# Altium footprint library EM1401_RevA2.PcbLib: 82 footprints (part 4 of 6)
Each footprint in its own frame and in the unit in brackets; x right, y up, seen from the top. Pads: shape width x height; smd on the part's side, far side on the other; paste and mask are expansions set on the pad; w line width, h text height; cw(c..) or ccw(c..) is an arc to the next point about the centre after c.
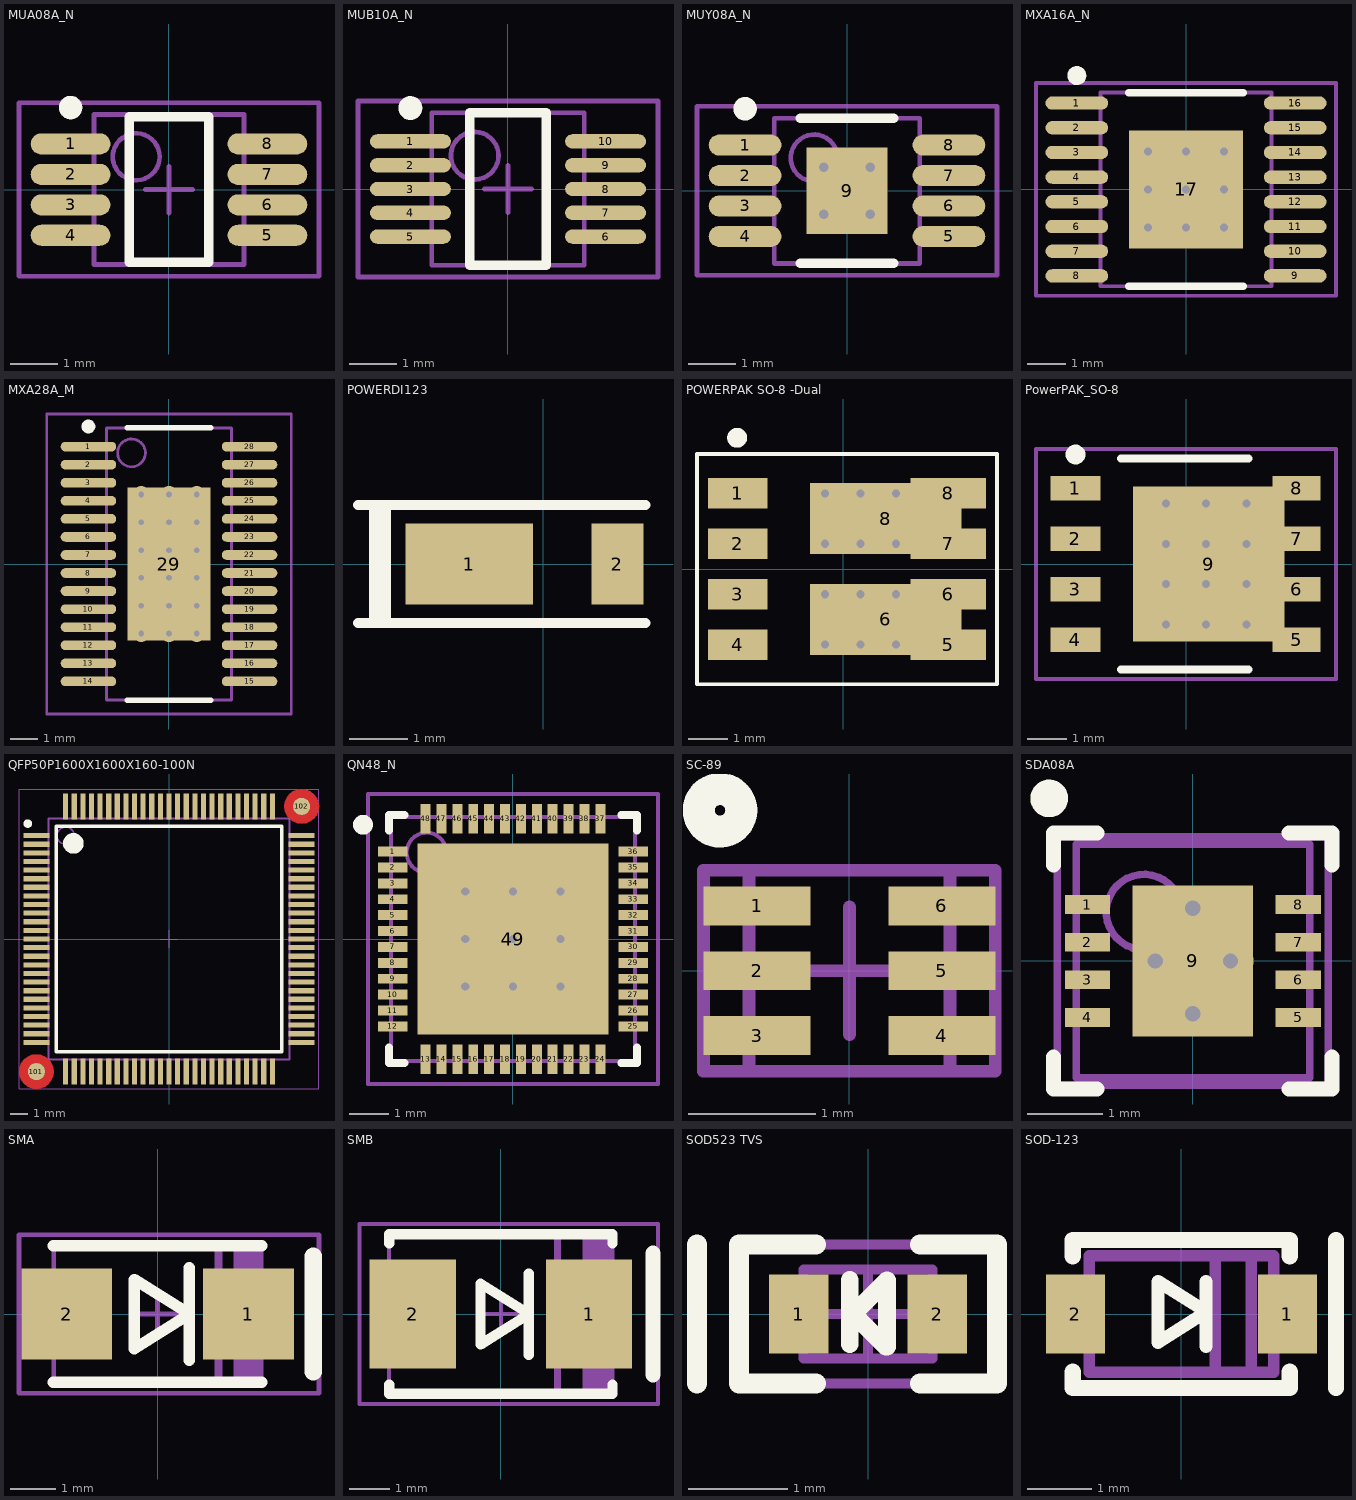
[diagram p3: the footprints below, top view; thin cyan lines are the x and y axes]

## MUA08A_N [mm] "TSOP, 8-Leads, Body 3x3mm, Pitch 0.65mm, IPC Medium Density"
height 1.09
pads (8):
  oval 1.7x0.45 smd: 1(-2.1,0.975) 2(-2.1,0.325) 3(-2.1,-0.325) 4(-2.1,-0.975) 5(2.1,-0.975) 6(2.1,-0.325) 7(2.1,0.325) 8(2.1,0.975)
Top Overlay:
  circle w0.25: c-2.1,1.75 r0.125
  lines w0.2: -0.85,-1.55 0.85,-1.55 0.85,1.55 -0.85,1.55 -0.85,-1.55
Mechanical 5:
  text ".Designator" at -1.524,-0.508 h1.02
Mechanical 13:
  circle w0.1: c-0.7,0.7 r0.5
  lines w0.1: -1.6,-1.6 1.6,-1.6 1.6,1.6 -1.6,1.6 -1.6,-1.6
Mechanical 15:
  lines w0.1: -0.5,0 0.5,0 ; 0,-0.5 0,0.5 ; -3.2,-1.85 3.2,-1.85 3.2,1.85 -3.2,1.85 -3.2,-1.85
3D body: height 1.09, standoff 0, extent -1.6,-1.6 1.6,1.6

## MUB10A_N [mm] "TSSOP, 10-Leads, Body 3x3mm, Pitch 0.5mm, IPC Medium Density"
height 1.09
pads (10):
  oval 1.7x0.3 smd: 1(-2.05,1) 2(-2.05,0.5) 3(-2.05,0) 4(-2.05,-0.5) 5(-2.05,-1) 6(2.05,-1) 7(2.05,-0.5) 8(2.05,0) 9(2.05,0.5) 10(2.05,1)
Top Overlay:
  circle w0.25: c-2.05,1.7 r0.125
  lines w0.2: -0.8,-1.6 -0.8,1.6 0.8,1.6 0.8,-1.6 -0.8,-1.6
Mechanical 5:
  text ".Designator" at -1.524,-0.508 h1.02
Mechanical 13:
  circle w0.1: c-0.7,0.7 r0.5
  lines w0.1: -1.6,-1.6 -1.6,1.6 1.6,1.6 1.6,-1.6 -1.6,-1.6
Mechanical 15:
  lines w0.1: -0.5,0 0.5,0 ; 0,-0.5 0,0.5 ; -3.15,-1.85 -3.15,1.85 3.15,1.85 3.15,-1.85 -3.15,-1.85
3D body: height 1.09, standoff 0, extent -1.6,-1.6 1.6,1.6

## MUY08A_N [mm] "TSOP, 8-Leads, Body 3x3mm, Pitch 0.65mm, Exposed Pad, IPC Medium Density"
height 1.09
pads (9):
  oval 1.55x0.45 smd: 1(-2.175,0.975) 2(-2.175,0.325) 3(-2.175,-0.325) 4(-2.175,-0.975) 5(2.175,-0.975) 6(2.175,-0.325) 7(2.175,0.325) 8(2.175,0.975)
  rect 1.73x1.85 smd: 9(0,0)
via 0.5,-0.5 diameter 0.61 hole 0.203
via -0.5,-0.5 diameter 0.61 hole 0.203
via -0.5,0.5 diameter 0.61 hole 0.203
via 0.5,0.5 diameter 0.61 hole 0.203
Top Overlay:
  circle w0.25: c-2.175,1.75 r0.125
  lines w0.2: -1,-1.55 1,-1.55 ; -1,1.55 1,1.55
Mechanical 5:
  text ".Designator" at -1.524,-0.508 h1.02
Mechanical 13:
  circle w0.1: c-0.7,0.7 r0.5
  lines w0.1: -1.55,-1.55 1.55,-1.55 1.55,1.55 -1.55,1.55 -1.55,-1.55
Mechanical 15:
  lines w0.1: -0.5,0 0.5,0 ; 0,-0.5 0,0.5 ; -3.2,-1.8 3.2,-1.8 3.2,1.8 -3.2,1.8 -3.2,-1.8
3D body: height 1.09, standoff 0, extent -1.549,-1.549 1.549,1.549

## MXA16A_N [mm] "TSOP, 16-Leads, Body 5x4.4mm, Pitch 0.65mm, Exposed Pad, IPC Medium Density"
height 1.1
pads (17):
  oval 1.65x0.35 smd: 1(-2.875,2.275) 2(-2.875,1.625) 3(-2.875,0.975) 4(-2.875,0.325) 5(-2.875,-0.325) 6(-2.875,-0.975) 7(-2.875,-1.625) 8(-2.875,-2.275) 9(2.875,-2.275) 10(2.875,-1.625) 11(2.875,-0.975) 12(2.875,-0.325) 13(2.875,0.325) 14(2.875,0.975) 15(2.875,1.625) 16(2.875,2.275)
  rect 3x3.1 smd: 17(0,0)
via -1,-1 diameter 0.61 hole 0.203
via 0,-1 diameter 0.61 hole 0.203
via -1,0 diameter 0.61 hole 0.203
via 0,0 diameter 0.61 hole 0.203
via 1,-1 diameter 0.61 hole 0.203
via 1,0 diameter 0.61 hole 0.203
via 0,1 diameter 0.61 hole 0.203
via -1,1 diameter 0.61 hole 0.203
via 1,1 diameter 0.61 hole 0.203
Top Overlay:
  circle w0.25: c-2.875,3 r0.125
  lines w0.2: -1.5,-2.55 1.5,-2.55 ; -1.5,2.55 1.5,2.55
Mechanical 5:
  text ".Designator" at -1.524,-0.508 h1.02
Mechanical 13:
  lines w0.1: -2.25,-2.55 2.25,-2.55 2.25,2.55 -2.25,2.55 -2.25,-2.55
Mechanical 15:
  lines w0.1: -0.5,0 0.5,0 ; 0,-0.5 0,0.5 ; -3.95,-2.8 3.95,-2.8 3.95,2.8 -3.95,2.8 -3.95,-2.8
3D body: height 1.1, standoff 0, extent -2.25,-2.55 2.25,2.55

## MXA28A_M [mm] "TSOP, 28-Leads, Body 9.7x4.4mm, Pitch 0.65mm, Exposed Pad, IPC Low Density"
height 1.1
pads (29):
  oval 2x0.35 smd: 1(-2.9,4.225) 2(-2.9,3.575) 3(-2.9,2.925) 4(-2.9,2.275) 5(-2.9,1.625) 6(-2.9,0.975) 7(-2.9,0.325) 8(-2.9,-0.325) 9(-2.9,-0.975) 10(-2.9,-1.625) 11(-2.9,-2.275) 12(-2.9,-2.925) 13(-2.9,-3.575) 14(-2.9,-4.225) 15(2.9,-4.225) 16(2.9,-3.575) 17(2.9,-2.925) 18(2.9,-2.275) 19(2.9,-1.625) 20(2.9,-0.975) 21(2.9,-0.325) 22(2.9,0.325) 23(2.9,0.975) 24(2.9,1.625) 25(2.9,2.275) 26(2.9,2.925) 27(2.9,3.575) 28(2.9,4.225)
  rect 3x5.5 smd: 29(0,0)
via 1,2.5 diameter 0.61 hole 0.203
via 1,1.5 diameter 0.61 hole 0.203
via 1,0.5 diameter 0.61 hole 0.203
via 1,-0.5 diameter 0.61 hole 0.203
via 1,-1.5 diameter 0.61 hole 0.203
via 1,-2.5 diameter 0.61 hole 0.203
via 0,2.5 diameter 0.61 hole 0.203
via 0,1.5 diameter 0.61 hole 0.203
via -1,2.5 diameter 0.61 hole 0.203
via -1,1.5 diameter 0.61 hole 0.203
via 0,0.5 diameter 0.61 hole 0.203
via -1,0.5 diameter 0.61 hole 0.203
via 0,-0.5 diameter 0.61 hole 0.203
via 0,-1.5 diameter 0.61 hole 0.203
via 0,-2.5 diameter 0.61 hole 0.203
via -1,-0.5 diameter 0.61 hole 0.203
via -1,-1.5 diameter 0.61 hole 0.203
via -1,-2.5 diameter 0.61 hole 0.203
Top Overlay:
  circle w0.25: c-2.9,4.95 r0.125
  lines w0.2: -1.5,-4.9 1.5,-4.9 ; -1.5,4.9 1.5,4.9
Mechanical 5:
  text ".Designator" at -1.524,-0.508 h1.02
Mechanical 13:
  circle w0.1: c-1.35,4 r0.5
  lines w0.1: -2.25,-4.9 2.25,-4.9 2.25,4.9 -2.25,4.9 -2.25,-4.9
Mechanical 15:
  lines w0.1: -4.4,-5.4 4.4,-5.4 4.4,5.4 -4.4,5.4 -4.4,-5.4 ; -0.5,0 0.5,0 -0.5,0 ; 0,-0.5 0,0.5 0,-0.5
3D body: height 1.1, standoff 0.05, extent -2.25,-4.9 2.25,4.9

## POWERDI123 [mm] "Diodes Inc recommended land pattern, document number DS30628 Rev. 6-2"
height 1
pads (2):
  rect 2.2x1.4 smd: 1(-1.275,0)
  rect 0.9x1.4 smd: 2(1.275,0)
Top Overlay:
  lines w0.178: -3.194,-1.016 1.759,-1.016 ; -3.194,1.016 1.759,1.016
  lines w0.381: -2.813,-0.889 -2.813,0.889
Mechanical 5:
  text ".Designator" at -1.524,-0.508 h1.02
3D body: height 1, standoff 0.9, extent -1.299,-0.799 -1.101,0.699
3D body: height 1, standoff 0, extent -1.499,-0.969 1.499,0.959

## POWERPAK SO-8 -Dual [mm] "Dual N-CHANNEL 40V MOSFET, POWERPAK SO-8 , VISHAY"
height 3.5
pads (10):
  rect 1.5x0.762 smd mask+0.076: 1(-2.65,1.905) 2(-2.65,0.635) 3(-2.65,-0.635) 4(-2.65,-1.905)
  rect 1.9x0.762 smd mask+0.076: 5(2.65,-1.905) 6(2.65,-0.635) 7(2.65,0.635) 8(2.65,1.905)
  rect 3.81x1.778 smd: 6(1.075,-1.27) 8(1.075,1.27)
via 0.44,-1.905 diameter 0.406 hole 0.203
via 1.329,-1.905 diameter 0.406 hole 0.203
via 1.329,-0.635 diameter 0.406 hole 0.203
via 1.329,0.635 diameter 0.406 hole 0.203
via 0.44,-0.635 diameter 0.406 hole 0.203
via -0.449,-1.905 diameter 0.406 hole 0.203
via -0.449,-0.635 diameter 0.406 hole 0.203
via -0.449,0.635 diameter 0.406 hole 0.203
via 0.44,0.635 diameter 0.406 hole 0.203
via 0.44,1.905 diameter 0.406 hole 0.203
via 1.329,1.905 diameter 0.406 hole 0.203
via -0.449,1.905 diameter 0.406 hole 0.203
Top Overlay:
  circle w0.25: c-2.665,3.302 r0.125
  lines w0.1: -3.675,-2.9 3.875,-2.9 3.875,2.9 -3.675,2.9 -3.675,-2.9
Mechanical 5:
  text ".designator" at 0.465,-2.08 h1.02

## PowerPAK_SO-8 [mil] "Vishay PowerPAK SO-8, Body 5.3x6.0mm (max), Pitch 1.27mm, IPC Medium Density"
height 44.09
pads (9):
  rect 50x24 smd mask+2.99: 1(-109.5,75) 2(-109.5,25) 3(-109.5,-25) 4(-109.5,-75)
  rect 48x24 smd mask+2.99: 5(109.5,-75) 8(109.5,75)
  rect 48x24 smd paste-12 mask+2.99: 6(109.5,-25) 7(109.5,25)
  rect 150x154 smd paste-75 mask+2.99: 9(22.5,0)
via 20,60 diameter 28 hole 8
via -20,60 diameter 28 hole 8
via -20,20 diameter 28 hole 8
via 20,20 diameter 28 hole 8
via 60,60 diameter 28 hole 8
via 60,20 diameter 28 hole 8
via -20,-20 diameter 28 hole 8
via 60,-20 diameter 28 hole 8
via 20,-20 diameter 28 hole 8
via 20,-60 diameter 28 hole 8
via -20,-60 diameter 28 hole 8
via 60,-60 diameter 28 hole 8
Top Overlay:
  circle w9.84: c-109.5,108.46 r4.92
  lines w7.87: -64.22,-104.33 61.76,-104.33 ; -64.22,104.33 61.76,104.33
Top Paste:
  rectangle: -47,2.5 20.5,72
  rectangle: 25.5,2.5 93,72
  rectangle: 97.5,13 133,37
  rectangle: 97.5,-37 133,-13
  rectangle: -47.5,-72 20,-2.5
  rectangle: 25,-72 92.5,-2.5
Mechanical 5:
  text ".Designator" at -60,-20 h40
Mechanical 15:
  lines w3.94: -19.68,0 19.68,0 ; 0,-19.68 0,19.68 ; -148.62,-114.17 -148.62,114.17 148.62,114.17 148.62,-114.17 -148.62,-114.17
3D body: height 42.6, standoff 0.6, extent -120.84,-101.5 121.16,101.5

## QFP50P1600X1600X160-100N [mm]
pads (102):
  rect 1.5x0.3 smd: 1(-7.7,6) 2(-7.7,5.5) 3(-7.7,5) 4(-7.7,4.5) 5(-7.7,4) 6(-7.7,3.5) 7(-7.7,3) 8(-7.7,2.5) 9(-7.7,2) 10(-7.7,1.5) 11(-7.7,1) 12(-7.7,0.5) 13(-7.7,0) 14(-7.7,-0.5) 15(-7.7,-1) 16(-7.7,-1.5) 17(-7.7,-2) 18(-7.7,-2.5) 19(-7.7,-3) 20(-7.7,-3.5) 21(-7.7,-4) 22(-7.7,-4.5) 23(-7.7,-5) 24(-7.7,-5.5) 25(-7.7,-6) 51(7.7,-6) 52(7.7,-5.5) 53(7.7,-5) 54(7.7,-4.5) 55(7.7,-4) 56(7.7,-3.5) 57(7.7,-3) 58(7.7,-2.5) 59(7.7,-2) 60(7.7,-1.5) 61(7.7,-1) 62(7.7,-0.5) 63(7.7,0) 64(7.7,0.5) 65(7.7,1) 66(7.7,1.5) 67(7.7,2) 68(7.7,2.5) 69(7.7,3) 70(7.7,3.5) 71(7.7,4) 72(7.7,4.5) 73(7.7,5) 74(7.7,5.5) 75(7.7,6)
  rect 0.3x1.5 smd: 26(-6,-7.7) 27(-5.5,-7.7) 28(-5,-7.7) 29(-4.5,-7.7) 30(-4,-7.7) 31(-3.5,-7.7) 32(-3,-7.7) 33(-2.5,-7.7) 34(-2,-7.7) 35(-1.5,-7.7) 36(-1,-7.7) 37(-0.5,-7.7) 38(0,-7.7) 39(0.5,-7.7) 40(1,-7.7) 41(1.5,-7.7) 42(2,-7.7) 43(2.5,-7.7) 44(3,-7.7) 45(3.5,-7.7) 46(4,-7.7) 47(4.5,-7.7) 48(5,-7.7) 49(5.5,-7.7) 50(6,-7.7) 76(6,7.7) 77(5.5,7.7) 78(5,7.7) 79(4.5,7.7) 80(4,7.7) 81(3.5,7.7) 82(3,7.7) 83(2.5,7.7) 84(2,7.7) 85(1.5,7.7) 86(1,7.7) 87(0.5,7.7) 88(0,7.7) 89(-0.5,7.7) 90(-1,7.7) 91(-1.5,7.7) 92(-2,7.7) 93(-2.5,7.7) 94(-3,7.7) 95(-3.5,7.7) 96(-4,7.7) 97(-4.5,7.7) 98(-5,7.7) 99(-5.5,7.7) 100(-6,7.7)
  round 1 smd mask+0.5: 101(-7.7,-7.7) 102(7.7,7.7)
Top Layer:
  region: -6.691,-7.7 -6.726,-7.439 -6.827,-7.196 -6.987,-6.987 -7.196,-6.827 -7.439,-6.726 -7.7,-6.691 -7.961,-6.726 -8.204,-6.827 -8.413,-6.987 -8.573,-7.196 -8.674,-7.439 -8.709,-7.7 -8.674,-7.961 -8.573,-8.204 -8.413,-8.413 -8.204,-8.573 -7.961,-8.674 -7.7,-8.709 -7.439,-8.674 -7.196,-8.573 -6.987,-8.413 -6.827,-8.204 -6.726,-7.961
  region: 8.709,7.7 8.674,7.961 8.573,8.204 8.413,8.413 8.204,8.573 7.961,8.674 7.7,8.709 7.439,8.674 7.196,8.573 6.987,8.413 6.827,8.204 6.726,7.961 6.691,7.7 6.726,7.439 6.827,7.196 6.987,6.987 7.196,6.827 7.439,6.726 7.7,6.691 7.961,6.726 8.204,6.827 8.413,6.987 8.573,7.196 8.674,7.439
Top Overlay:
  circle w0.25: c-8.2,6.7 r0.125
  circle w0.6: c-5.55,5.55 r0.3
  lines w0.2: -6.55,-6.55 -6.55,6.55 6.55,6.55 6.55,-6.55 -6.55,-6.55
Mechanical 15:
  circle w0.1: c-6,6 r0.5
  lines w0.1: -7,-7 -7,7 7,7 7,-7 -7,-7
Mechanical 16:
  lines w0.001: -7,-7 -7,7 7,7 7,-7 -7,-7
  lines w0.05: -0.5,0 0.5,0 ; 0,-0.5 0,0.5 ; -8.7,-8.7 -8.7,8.7 8.7,8.7 8.7,-8.7 -8.7,-8.7

## QN48_N [mm] "QFN, 48-Leads, Body 6x6 mm, Pitch 0.4mm, IPC Medium Density"
height 1
pads (49):
  rect 0.75x0.25 smd: 1(-3.025,2.2) 2(-3.025,1.8) 3(-3.025,1.4) 4(-3.025,1) 5(-3.025,0.6) 6(-3.025,0.2) 7(-3.025,-0.2) 8(-3.025,-0.6) 9(-3.025,-1) 10(-3.025,-1.4) 11(-3.025,-1.8) 12(-3.025,-2.2) 25(3.025,-2.2) 26(3.025,-1.8) 27(3.025,-1.4) 28(3.025,-1) 29(3.025,-0.6) 30(3.025,-0.2) 31(3.025,0.2) 32(3.025,0.6) 33(3.025,1) 34(3.025,1.4) 35(3.025,1.8) 36(3.025,2.2)
  rect 0.25x0.75 smd: 13(-2.2,-3.025) 14(-1.8,-3.025) 15(-1.4,-3.025) 16(-1,-3.025) 17(-0.6,-3.025) 18(-0.2,-3.025) 19(0.2,-3.025) 20(0.6,-3.025) 21(1,-3.025) 22(1.4,-3.025) 23(1.8,-3.025) 24(2.2,-3.025) 37(2.2,3.025) 38(1.8,3.025) 39(1.4,3.025) 40(1,3.025) 41(0.6,3.025) 42(0.2,3.025) 43(-0.2,3.025) 44(-0.6,3.025) 45(-1,3.025) 46(-1.4,3.025) 47(-1.8,3.025) 48(-2.2,3.025)
  rect 4.8x4.8 smd paste-2.4 mask+0.062: 49(0,0)
via -1.2,1.2 diameter 0.508 hole 0.203
via 0,0 diameter 0.508 hole 0.203
via 1.2,1.2 diameter 0.508 hole 0.203
via 0,1.2 diameter 0.508 hole 0.203
via 1.2,-1.2 diameter 0.508 hole 0.203
via -1.2,-1.2 diameter 0.508 hole 0.203
via 0,-1.2 diameter 0.508 hole 0.203
via -1.2,0 diameter 0.508 hole 0.203
via 1.2,0 diameter 0.508 hole 0.203
Top Overlay:
  circle w0.25: c-3.775,2.875 r0.125
  lines w0.2: -3.125,-2.725 -3.125,-3.125 -2.725,-3.125 ; -3.125,2.725 -3.125,3.125 -2.725,3.125 ; 2.725,-3.125 3.125,-3.125 3.125,-2.725 ; 2.725,3.125 3.125,3.125 3.125,2.725
Top Paste:
  rectangle: 0.1,-1.1 1.1,-0.1
  rectangle: 1.3,-2.3 2.3,-1.3
  rectangle: 1.3,-1.1 2.3,-0.1
  rectangle: 0.1,-2.3 1.1,-1.3
  region: -0.1,-0.1 -1.1,-0.1 -1.1,-1.1 -0.1,-1.1
  region: -1.3,-1.3 -2.3,-1.3 -2.3,-2.3 -1.3,-2.3
  region: -1.309,-0.1 -2.309,-0.1 -2.309,-1.1 -1.309,-1.1
  region: -0.1,-1.3 -1.1,-1.3 -1.1,-2.3 -0.1,-2.3
  region: -0.1,1.1 -1.1,1.1 -1.1,0.1 -0.1,0.1
  region: -1.3,2.3 -2.3,2.3 -2.3,1.3 -1.3,1.3
  region: -1.3,1.1 -2.3,1.1 -2.3,0.1 -1.3,0.1
  region: -0.1,2.3 -1.1,2.3 -1.1,1.3 -0.1,1.3
  rectangle: 0.1,1.3 1.1,2.3
  rectangle: 1.3,0.1 2.3,1.1
  rectangle: 1.3,1.3 2.3,2.3
  rectangle: 0.1,0.1 1.1,1.1
Mechanical 13:
  circle w0.1: c-2.175,2.175 r0.5
  lines w0.1: -3.075,-3.075 -3.075,3.075 3.075,3.075 3.075,-3.075 -3.075,-3.075
Mechanical 15:
  lines w0.1: -0.5,0 0.5,0 ; 0,-0.5 0,0.5 ; -3.65,-3.65 -3.65,3.65 3.65,3.65 3.65,-3.65 -3.65,-3.65
3D body: height 1, standoff 0, extent -3.074,-3.074 3.074,3.074

## SC-89 [mil] "SOT23, 5-Leads, Body .5mm pitch 1.5mm x 1.5mm body"
height 19.68
pads (6):
  rect 33x12 smd: 1(-28.5,20) 2(-28.5,0) 3(-28.5,-20) 4(28.5,-20) 5(28.5,0) 6(28.5,20)
Top Overlay:
  circle w9.84: c-39.92,49.5 r6.58
Mechanical 5:
  text ".designator" at 0,0 h40
Mechanical 13:
  lines w3.94: -31,-31 -31,31 31,31 31,-31 -31,-31
Mechanical 15:
  lines w3.94: -19.68,0 19.68,0 ; 0,-19.68 0,19.69 ; -45,-31 -45,31 45,31 45,-31 -45,-31
3D body: height 48.03, standoff 0, extent -31,-31 31,31

## SDA08A [mm] "SON, 8-Leads, Body 3x3mm, Pitch 0.5mm, NSC Recommended"
height 0.8
pads (9):
  rect 0.6x0.25 smd paste-0.125 mask+0.051: 1(-1.4,0.75) 2(-1.4,0.25) 3(-1.4,-0.25) 4(-1.4,-0.75) 5(1.4,-0.75) 6(1.4,-0.25) 7(1.4,0.25) 8(1.4,0.75)
  rect 1.6x2 smd paste-0.05 mask+0.051: 9(0,0)
via -0.5,0 diameter 0.61 hole 0.203
via 0,-0.7 diameter 0.61 hole 0.203
via 0,0.7 diameter 0.61 hole 0.203
via 0.5,0 diameter 0.61 hole 0.203
Top Overlay:
  circle w0.25: c-1.907,2.159 r0.125
  lines w0.2: -1.85,-1.275 -1.85,-1.7 -1.275,-1.7 ; -1.85,1.275 -1.85,1.7 -1.275,1.7 ; 1.275,-1.7 1.85,-1.7 1.85,-1.275 ; 1.275,1.7 1.85,1.7 1.85,1.275
Top Paste:
  region: -1.9,-0.125 -1.9,-0.375 -1.2,-0.375 -1.2,-0.125
  region: -1.9,0.375 -1.9,0.125 -1.2,0.125 -1.2,0.375
  region: -1.9,-0.625 -1.9,-0.875 -1.2,-0.875 -1.2,-0.625
  region: -1.9,0.875 -1.9,0.625 -1.2,0.625 -1.2,0.875
  region: 1.2,-0.625 1.2,-0.875 1.9,-0.875 1.9,-0.625
  region: 1.2,0.375 1.2,0.125 1.9,0.125 1.9,0.375
  region: 1.2,-0.125 1.2,-0.375 1.9,-0.375 1.9,-0.125
  region: 1.2,0.875 1.2,0.625 1.9,0.625 1.9,0.875
Mechanical 5:
  text ".Designator" at -1.524,-0.508 h1.02
Mechanical 13:
  circle w0.1: c-0.65,0.65 r0.5
  lines w0.1: -1.55,-1.55 -1.55,1.55 1.55,1.55 1.55,-1.55 -1.55,-1.55
Mechanical 15:
  lines w0.1: -0.5,0 0.5,0 ; 0,-0.5 0,0.5 ; -1.8,-1.65 -1.8,1.65 1.8,1.65 1.8,-1.65 -1.8,-1.65
3D body: height 0.8, standoff 0, extent -1.55,-1.55 1.55,1.55

## SMA [mm] "Molded Diode, 2-Leads, Body 4.3x2.6mm, IPC Medium Density, based on OnSemi component dimensions and land pattern"
height 2.27
pads (2):
  rect 2x2 smd: 1(2,0) 2(-2,0)
Top Overlay:
  lines w0.254: -2.3,-1.5 2.3,-1.5 ; -2.3,1.5 2.3,1.5 ; 0.698,-1.022 0.698,1.016 ; 0.698,-0.004 -0.512,-0.766 -0.507,0.758 0.698,0.006
  lines w0.381: 3.429,-1.27 3.429,1.27
Mechanical 5:
  text ".Designator" at -1.524,-0.508 h1.02
Mechanical 13:
  rectangle: 1.673,-1.464 2.287,1.456
  lines w0.1: -2.285,-1.46 -2.285,1.46 2.285,1.46 2.285,-1.46 -2.285,-1.46
  lines w0.178: 1.346,-1.46 1.346,1.46 ; 1.905,-1.46 1.905,1.46
Mechanical 15:
  lines w0.1: -0.5,0 0.5,0 ; 0,-0.5 0,0.5 ; -3.05,-1.75 -3.05,1.75 3.556,1.75 3.556,-1.75 -3.05,-1.75
3D body: height 2.27, standoff 2.2, extent 1.347,-1.459 1.904,1.459
3D body: height 2.27, standoff 0, extent -2.285,-1.46 2.285,1.46

## SMB [mm] "Molded Diode, 2-Leads, Body 5.4x3.6mm, IPC Medium Density, based on OnSemi component dimensions"
height 2.45
pads (2):
  rect 2.159x2.743 smd: 1(2.21,0) 2(-2.21,0)
Top Overlay:
  lines w0.254: -2.8,-1.772 -2.8,-2 2.8,-2 2.8,-1.772 ; -2.8,1.772 -2.8,2 2.8,2 2.8,1.772 ; 0.698,-1.021 0.698,1.016 ; 0.698,-0.004 -0.512,-0.766 -0.507,0.758 0.698,0.006
  lines w0.381: 3.81,-1.524 3.81,1.524
Mechanical 5:
  text ".Designator" at -1.524,-0.508 h1.02
Mechanical 13:
  rectangle: 2.047,-1.975 2.8,1.975
  lines w0.1: -2.8,-1.975 -2.8,1.975 2.8,1.975 2.8,-1.975 -2.8,-1.975
  lines w0.178: 1.422,-1.975 1.422,1.975 ; 2.261,-1.975 2.261,1.975
Mechanical 15:
  lines w0.1: -0.5,0 0.5,0 ; 0,-0.5 0,0.5 ; -3.55,-2.25 -3.55,2.25 3.937,2.25 3.937,-2.25 -3.55,-2.25
3D body: height 2.45, standoff 2.44, extent 1.423,-1.974 2.26,1.974
3D body: height 2.45, standoff 0, extent -2.8,-1.975 2.8,1.975

## SOD523 TVS [mm] "SOD footpirnt - TVS ESD Bidirectional"
height 0.7
pads (2):
  rect 0.6x0.8 smd: 1(-0.7,0) 2(0.7,0)
Top Overlay:
  lines w0.178: -0.187,-0.305 -0.187,0.343 ; -0.15,0 0.18,-0.33 0.191,-0.33 0.191,0.341 -0.15,0
  lines w0.2: -1.725,-0.7 -1.725,0.7 ; -0.525,-0.7 -1.3,-0.7 -1.3,0.7 -0.525,0.7 ; 0.525,-0.7 1.3,-0.7 1.3,0.7 0.525,0.7
Mechanical 5:
  text ".designator" at -1.38,-0.665 h1.02
Mechanical 13:
  lines w0.1: -0.65,-0.45 0.65,-0.45 0.65,0.45 -0.65,0.45 -0.65,-0.45
Mechanical 15:
  lines w0.1: -0.45,0 0.45,0 ; 0,-0.45 0,0.45 ; -1.3,-0.7 1.3,-0.7 1.3,0.7 -1.3,0.7 -1.3,-0.7
3D body: height 0.7, standoff 0, extent -0.65,-0.45 0.65,0.45

## SOD-123 [mm] "On Semi recommended land pattern"
height 1.35
pads (2):
  rect 0.915x1.22 smd: 1(1.637,0) 2(-1.637,0)
Top Overlay:
  lines w0.2: 0.381,0.03 -0.362,-0.438 -0.359,0.502 0.381,0.039
  lines w0.203: 0.381,-0.5 0.381,0.5
  lines w0.254: -1.676,-0.889 -1.676,-1.143 1.676,-1.143 1.676,-0.889 ; -1.676,0.889 -1.676,1.143 1.676,1.143 1.676,0.889 ; 2.388,-1.143 2.388,1.143
Mechanical 5:
  text ".Designator" at -1.524,-0.508 h1.02
Mechanical 13:
  lines w0.178: 0.525,-0.902 0.525,0.902 ; 1.075,-0.902 1.075,0.902 ; -1.422,-0.902 1.422,-0.902 1.422,0.902 -1.422,0.902 -1.422,-0.902
3D body: height 1.35, standoff 1.35, extent 0.526,-0.901 1.074,0.901
3D body: height 1.35, standoff 0, extent -1.422,-0.901 1.422,0.901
